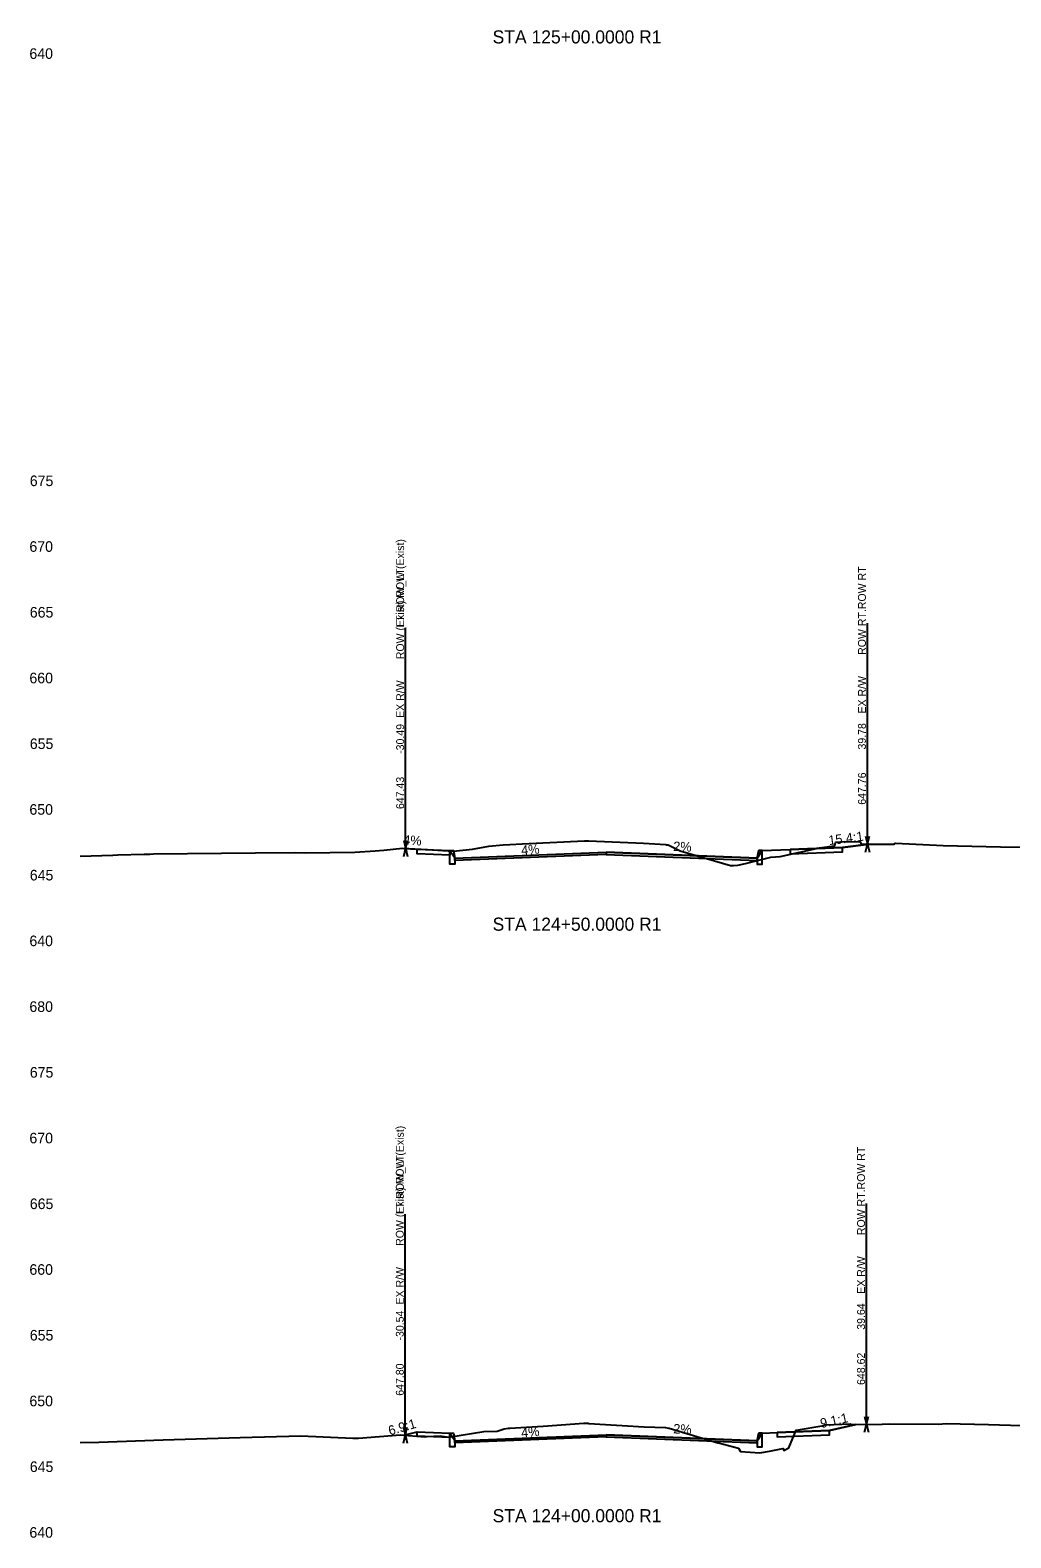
# Model space of a CAD drawing. Extents: x 2 to 741, y 16 to 2207.
# Drawn here: x 2.4 to 151.6, y 1155 to 1384.4 of the extents above; entities that cross this region are included whole.
import ezdxf

# ---------------------------------------------------------------- set-up
doc = ezdxf.new("R2010")
doc.units = 0
for name, color, linetype in [('Draft_XS_Feature_Name', 7, 'Continuous'), ('Draft_XS_Label', 7, 'Continuous'), ('Draft_XS_Point_Label_Indicator', 7, 'Continuous'), ('Draft_XS_Terminator', 7, 'Continuous'), ('Draft_XS_Text', 7, 'Continuous'), ('E_ROW', 7, 'Continuous'), ('E_Terrain_Exterior', 7, 'Continuous'), ('E_Terrain_Points_Low', 7, 'Continuous'), ('Grade_Veg_Grass', 7, 'Continuous'), ('P_XS_Sections', 7, 'Continuous'), ('Road_Curb', 7, 'Continuous'), ('Road_Pave_Asphalt', 7, 'Continuous'), ('Road_Sidewalk', 7, 'Continuous'), ('Terrain_Design', 7, 'Continuous')]:
    doc.layers.add(name, color=color, linetype=linetype)

msp = doc.modelspace()

# ---------------------------------------------------------------- linework, layer by layer
at = {"layer": 'Draft_XS_Terminator'}
for p, q in [((129.78, 1260.52), (129.78, 1282.52)), ((59.51, 1259.86), (59.51, 1281.86)), ((59.51, 1259.86), (59.51, 1281.86)), ((129.64, 1172.24), (129.64, 1194.24)), ((59.46, 1170.6), (59.46, 1192.6)), ((59.46, 1170.6), (59.46, 1192.6))]:
    msp.add_line(p, q, dxfattribs=at)
at = {"layer": 'E_ROW'}
for p, q in [((129.78, 1260.52), (129.78, 1294.12)), ((59.51, 1259.86), (59.51, 1293.46)), ((59.51, 1259.86), (59.51, 1293.46)), ((129.48, 1259.32), (130.08, 1261.72)), ((129.48, 1261.72), (130.08, 1259.32)), ((59.21, 1258.66), (59.81, 1261.06)), ((59.21, 1261.06), (59.81, 1258.66)), ((59.21, 1258.66), (59.81, 1261.06)), ((59.21, 1261.06), (59.81, 1258.66)), ((129.64, 1172.24), (129.64, 1205.84)), ((59.46, 1170.6), (59.46, 1204.2)), ((59.46, 1170.6), (59.46, 1204.2)), ((129.34, 1171.04), (129.94, 1173.44)), ((129.34, 1173.44), (129.94, 1171.04)), ((59.16, 1169.4), (59.76, 1171.8)), ((59.16, 1171.8), (59.76, 1169.4)), ((59.16, 1169.4), (59.76, 1171.8)), ((59.16, 1171.8), (59.76, 1169.4))]:
    msp.add_line(p, q, dxfattribs=at)
at = {"layer": 'E_Terrain_Exterior'}
for points in [[(10, 1258.7), (14.97, 1258.86), (15.72, 1258.89), (19.71, 1259), (20.58, 1259.02), (21.15, 1259.04), (36.65, 1259.18), (42.63, 1259.26), (44.21, 1259.22), (51.76, 1259.3), (54.87, 1259.51), (56.2, 1259.6), (59.03, 1259.89), (62.81, 1259.7), (66.75, 1259.45), (69.66, 1259.78), (72.18, 1260.21), (74.37, 1260.42), (75.37, 1260.49), (77.25, 1260.59), (86.72, 1261.03), (86.8, 1261.03), (87.27, 1261.02), (87.38, 1261.01), (95.71, 1260.67), (99.11, 1260.46), (99.2, 1260.41), (99.43, 1260.41), (101.29, 1259.52), (108.94, 1257.25), (109.38, 1257.25), (110.05, 1257.35), (111.21, 1257.58), (115.09, 1258.54), (116.51, 1258.64), (122.49, 1259.94), (123.97, 1260.18), (124.74, 1260.27), (124.8, 1260.34), (124.91, 1260.71), (124.96, 1260.84), (126.35, 1260.92), (128.69, 1260.86), (128.76, 1260.69), (128.89, 1260.51), (130.16, 1260.53), (130.18, 1260.53), (130.21, 1260.53), (130.36, 1260.53), (130.54, 1260.53), (130.58, 1260.53), (130.59, 1260.53), (130.61, 1260.53), (130.62, 1260.53), (130.88, 1260.53), (131.23, 1260.53), (131.3, 1260.53), (131.37, 1260.53), (131.91, 1260.53), (132.77, 1260.53), (132.92, 1260.54), (133.07, 1260.54), (133.81, 1260.54), (133.88, 1260.58), (134.05, 1260.67), (141.28, 1260.32), (150.04, 1260.1), (162.21, 1259.92)], [(10, 1169.5), (12.84, 1169.54), (22.62, 1169.87), (34.33, 1170.25), (43.55, 1170.52), (51.47, 1170.16), (51.62, 1170.12), (51.65, 1170.12), (51.83, 1170.12), (52.12, 1170.12), (52.14, 1170.12), (52.2, 1170.12), (52.26, 1170.12), (52.31, 1170.12), (58.73, 1170.67), (62.41, 1170.33), (62.79, 1170.39), (64.74, 1170.5), (66.06, 1170.31), (71.4, 1171.14), (73.41, 1171.22), (74.48, 1171.54), (75.15, 1171.64), (75.33, 1171.64), (75.37, 1171.68), (80.43, 1171.99), (86.62, 1172.41), (86.85, 1172.41), (87.26, 1172.41), (87.4, 1172.4), (95.82, 1171.88), (99.06, 1171.75), (99.52, 1171.69), (99.61, 1171.69), (107.02, 1169.43), (107.11, 1169.41), (110.17, 1168.6), (110.47, 1168.09), (113.39, 1167.9), (114.87, 1168.19), (116.91, 1168.55), (116.94, 1168.58), (117.07, 1168.27), (117.81, 1168.67), (118.93, 1171.35), (123.13, 1172.06), (123.23, 1172.18), (124.64, 1172.22), (127.12, 1172.34), (127.34, 1172.2), (132, 1172.29), (133.13, 1172.32), (140.61, 1172.27), (141.74, 1172.38), (148.19, 1172.21), (163.22, 1171.78)]]:
    msp.add_lwpolyline(points, dxfattribs=at)
at = {"layer": 'Grade_Veg_Grass'}
for points in [[(59.25, 1259.88), (61.25, 1259.74), (61.25, 1259.74)], [(113.75, 1259.54), (118, 1259.71)], [(130, 1260.52), (126, 1260.03), (126, 1260.03)], [(128.02, 1172.21), (128.02, 1172.21), (124.02, 1171.33)], [(59.25, 1170.62), (59.25, 1170.62), (61.25, 1171.12)], [(113.75, 1170.92), (116.02, 1171.01)]]:
    msp.add_lwpolyline(points, dxfattribs=at)
at = {"layer": 'Road_Curb'}
for points in [[(67, 1258.37), (67, 1257.46), (66.25, 1257.46), (66.25, 1259.54), (66.77, 1259.54), (67, 1258.37)], [(113, 1258.37), (113, 1257.46), (113.75, 1257.46), (113.75, 1259.54), (113.23, 1259.54), (113, 1258.37)], [(67, 1169.75), (67, 1168.84), (66.25, 1168.84), (66.25, 1170.92), (66.77, 1170.92), (67, 1169.75)], [(113, 1169.75), (113, 1168.84), (113.75, 1168.84), (113.75, 1170.92), (113.23, 1170.92), (113, 1169.75)]]:
    msp.add_lwpolyline(points, dxfattribs=at)
at = {"layer": 'Road_Pave_Asphalt'}
for points in [[(90, 1259.29), (90, 1258.96), (67, 1258.04), (67, 1258.37), (90, 1259.29)], [(90, 1259.29), (90, 1258.96), (113, 1258.04), (113, 1258.37), (90, 1259.29)], [(90, 1170.67), (90, 1170.34), (67, 1169.42), (67, 1169.75), (90, 1170.67)], [(90, 1170.67), (90, 1170.34), (113, 1169.42), (113, 1169.75), (90, 1170.67)]]:
    msp.add_lwpolyline(points, dxfattribs=at)
at = {"layer": 'Road_Sidewalk'}
for points in [[(66.25, 1259.54), (66.25, 1258.87), (61.25, 1259.07), (61.25, 1259.74), (66.25, 1259.54)], [(118, 1259.71), (118, 1259.04), (126, 1259.36), (126, 1260.03), (118, 1259.71)], [(66.25, 1170.92), (66.25, 1170.25), (61.25, 1170.45), (61.25, 1171.12), (66.25, 1170.92)], [(116.02, 1171.01), (116.02, 1170.34), (124.02, 1170.66), (124.02, 1171.33), (116.02, 1171.01)]]:
    msp.add_lwpolyline(points, dxfattribs=at)
at = {"layer": 'Terrain_Design'}
for points in [[(59.25, 1259.88), (59.25, 1259.88), (61.25, 1259.74), (66.25, 1259.54), (66.77, 1259.54), (67, 1258.37), (90, 1259.29), (113, 1258.37), (113.23, 1259.54), (113.75, 1259.54), (118, 1259.71), (126, 1260.03), (130, 1260.52)], [(59.25, 1259.88), (59.25, 1259.88), (61.25, 1259.74), (66.25, 1259.54), (66.77, 1258.73), (67, 1258.37), (90, 1259.29), (113, 1258.37), (113.23, 1258.73), (113.75, 1259.54), (118, 1259.71), (126, 1260.03), (130, 1260.52)], [(59.25, 1170.62), (61.25, 1171.12), (66.25, 1170.92), (66.77, 1170.92), (67, 1169.75), (90, 1170.67), (113, 1169.75), (113.23, 1170.92), (113.75, 1170.92), (116.02, 1171.01), (124.02, 1171.33), (128.02, 1172.21)], [(59.25, 1170.62), (61.25, 1171.12), (66.25, 1170.92), (66.77, 1170.11), (67, 1169.75), (90, 1170.67), (113, 1169.75), (113.23, 1170.11), (113.75, 1170.92), (116.02, 1171.01), (124.02, 1171.33), (128.02, 1172.21)]]:
    msp.add_lwpolyline(points, dxfattribs=at)

# ---------------------------------------------------------------- texts
at = {"layer": 'Draft_XS_Feature_Name'}
for s, p in [('ROW (Exist).ROW (Exist)', (59.27, 1288.66)), ('ROW_LT.ROW_LT', (59.27, 1288.66)), ('ROW RT.ROW RT', (129.54, 1289.32)), ('ROW (Exist).ROW (Exist)', (59.22, 1199.4)), ('ROW RT.ROW RT', (129.4, 1201.04)), ('ROW_LT.ROW_LT', (59.22, 1199.4))]:
    msp.add_text(s, height=1.2, rotation=90, dxfattribs=at).set_placement(p)
at = {"layer": 'Draft_XS_Label'}
for s, p in [('-30.49', (59.27, 1274.26)), ('-30.49', (59.27, 1274.26)), ('39.78', (129.54, 1274.92)), ('647.76', (129.54, 1266.52)), ('647.43', (59.27, 1265.86)), ('647.43', (59.27, 1265.86)), ('39.64', (129.4, 1186.64)), ('-30.54', (59.22, 1185)), ('-30.54', (59.22, 1185)), ('647.80', (59.22, 1176.6)), ('647.80', (59.22, 1176.6)), ('648.62', (129.4, 1178.24))]:
    msp.add_text(s, height=1.2, rotation=90, dxfattribs=at).set_placement(p)
at = {"layer": 'Draft_XS_Point_Label_Indicator'}
for p in [(59.24, 1259.86), (61.24, 1259.73), (66.24, 1259.53), (66.76, 1259.53), (113.22, 1259.53), (113.74, 1259.53), (117.99, 1259.7), (125.99, 1260.02), (129.99, 1260.51), (66.99, 1258.36), (66.99, 1257.44), (112.99, 1258.36), (112.99, 1257.44), (128, 1172.2), (59.24, 1170.61), (61.24, 1171.11), (66.24, 1170.91), (66.76, 1170.91), (113.22, 1170.91), (113.74, 1170.91), (116, 1171), (124, 1171.32), (66.99, 1169.74), (66.99, 1168.82), (112.99, 1169.74), (112.99, 1168.82)]:
    msp.add_text('X', height=0.024, dxfattribs=at).set_placement(p)
at = {"layer": 'Draft_XS_Text'}
for s, height, p in [('STA 125+00.0000 R1', 1.992, (72.74, 1382.35)), ('640', 1.608, (2.26, 1380)), ('675', 1.608, (2.32, 1315)), ('670', 1.608, (2.26, 1305)), ('665', 1.608, (2.32, 1295)), ('660', 1.608, (2.26, 1285)), ('655', 1.608, (2.32, 1275)), ('650', 1.608, (2.26, 1265)), ('645', 1.608, (2.32, 1255)), ('STA 124+50.0000 R1', 1.992, (72.74, 1247.35)), ('640', 1.608, (2.26, 1245)), ('680', 1.608, (2.26, 1235)), ('675', 1.608, (2.32, 1225)), ('670', 1.608, (2.26, 1215)), ('665', 1.608, (2.32, 1205)), ('660', 1.608, (2.26, 1195)), ('655', 1.608, (2.32, 1185)), ('650', 1.608, (2.26, 1175)), ('645', 1.608, (2.32, 1165)), ('STA 124+00.0000 R1', 1.992, (72.74, 1157.35)), ('640', 1.608, (2.26, 1155))]:
    msp.add_text(s, height=height, dxfattribs=at).set_placement(p)
for s, rotation, p in [('4%', 355.9569, (59.11, 1260.49)), ('15.4:1', 7.4052, (123.93, 1260.37)), ('4%', 4.5657, (77.14, 1258.87)), ('2%', 357.7094, (100.21, 1259.49)), ('6.9:1', 16.1604, (57.11, 1170.55)), ('2%', 357.7094, (100.21, 1170.87)), ('9.1:1', 12.4315, (122.76, 1171.67)), ('4%', 4.5657, (77.14, 1170.25))]:
    msp.add_text(s, height=1.44, rotation=rotation, dxfattribs=at).set_placement(p)
at = {"layer": 'E_ROW'}
for p in [(59.27, 1279.74), (59.27, 1279.74), (129.54, 1280.4), (129.4, 1192.12), (59.22, 1190.48), (59.22, 1190.48)]:
    msp.add_text('EX R/W', height=1.2, rotation=90, dxfattribs=at).set_placement(p)
at = {"layer": 'E_Terrain_Points_Low'}
for p in [(89.99, 1259.28), (89.99, 1170.66)]:
    msp.add_text('X', height=0.024, dxfattribs=at).set_placement(p)
at = {"layer": 'P_XS_Sections'}
for p in [(10, 1380), (10, 1245), (10, 1155)]:
    msp.add_text('-', height=0.0001, dxfattribs=at).set_placement(p)

doc.saveas('drawing.dxf')
